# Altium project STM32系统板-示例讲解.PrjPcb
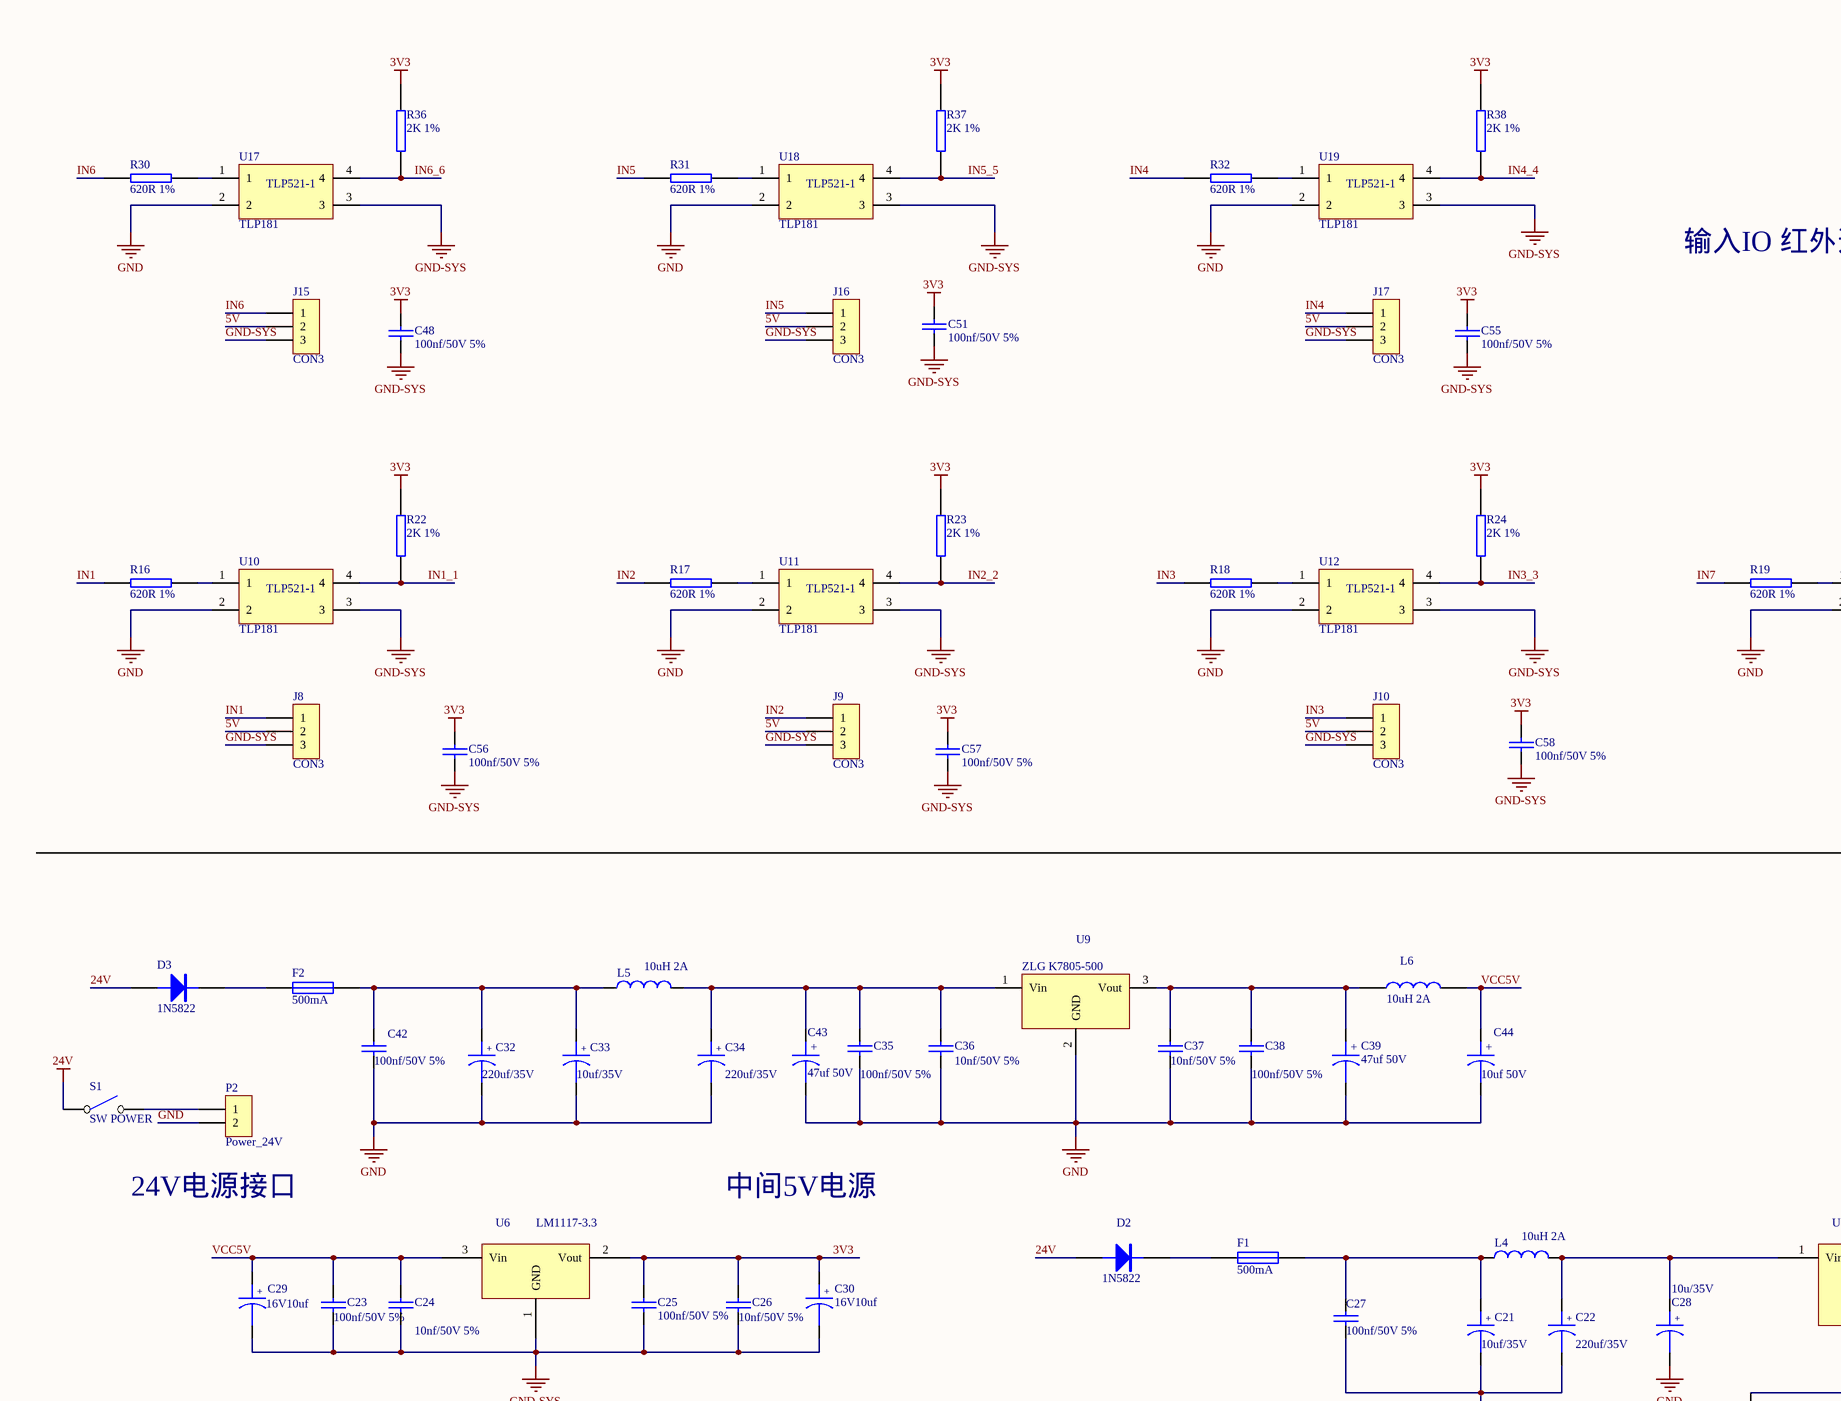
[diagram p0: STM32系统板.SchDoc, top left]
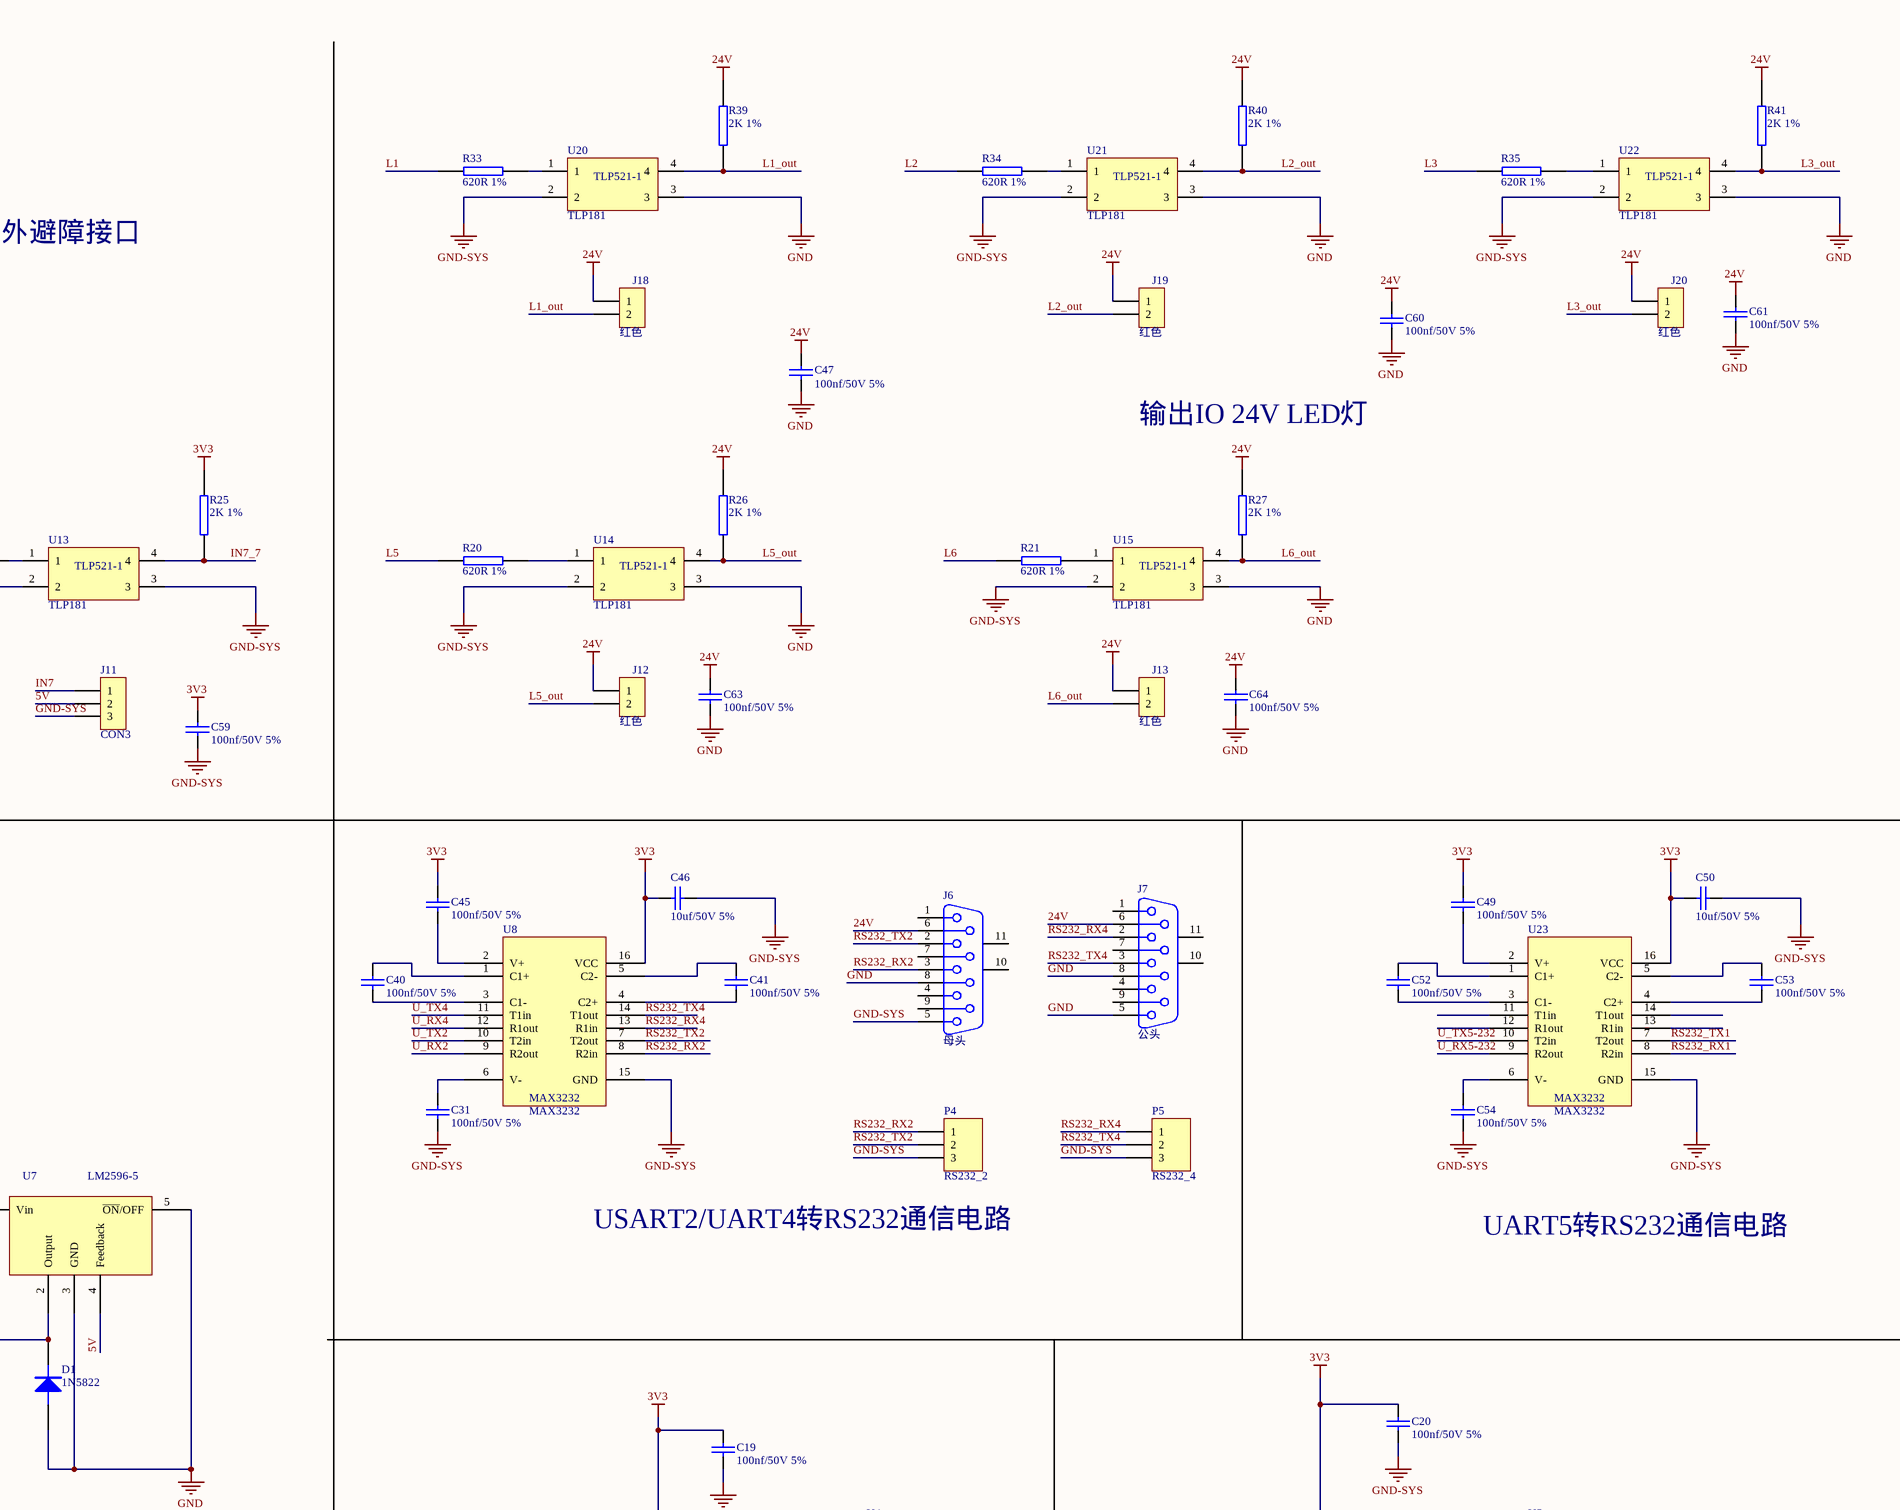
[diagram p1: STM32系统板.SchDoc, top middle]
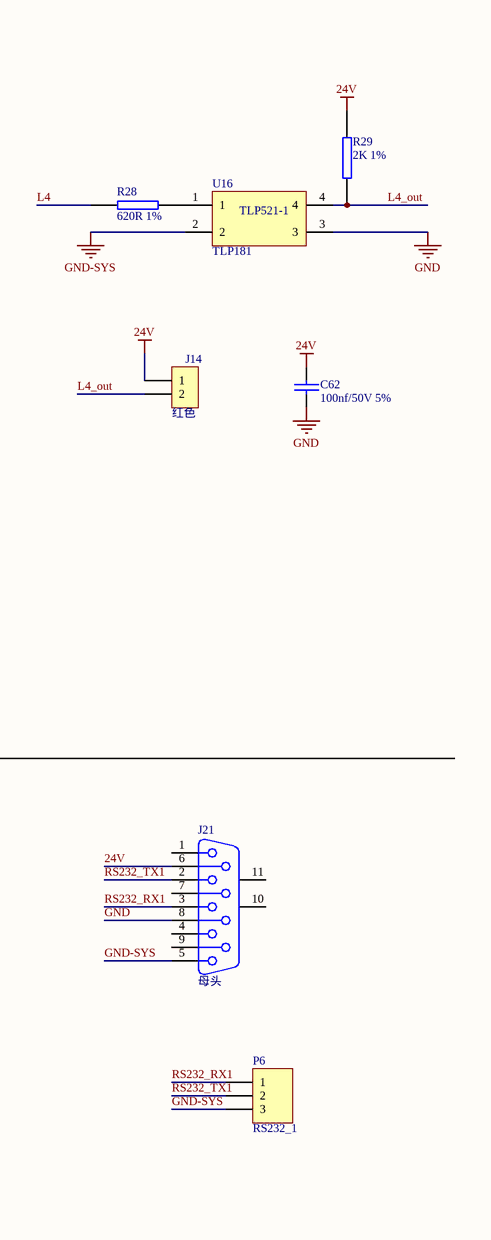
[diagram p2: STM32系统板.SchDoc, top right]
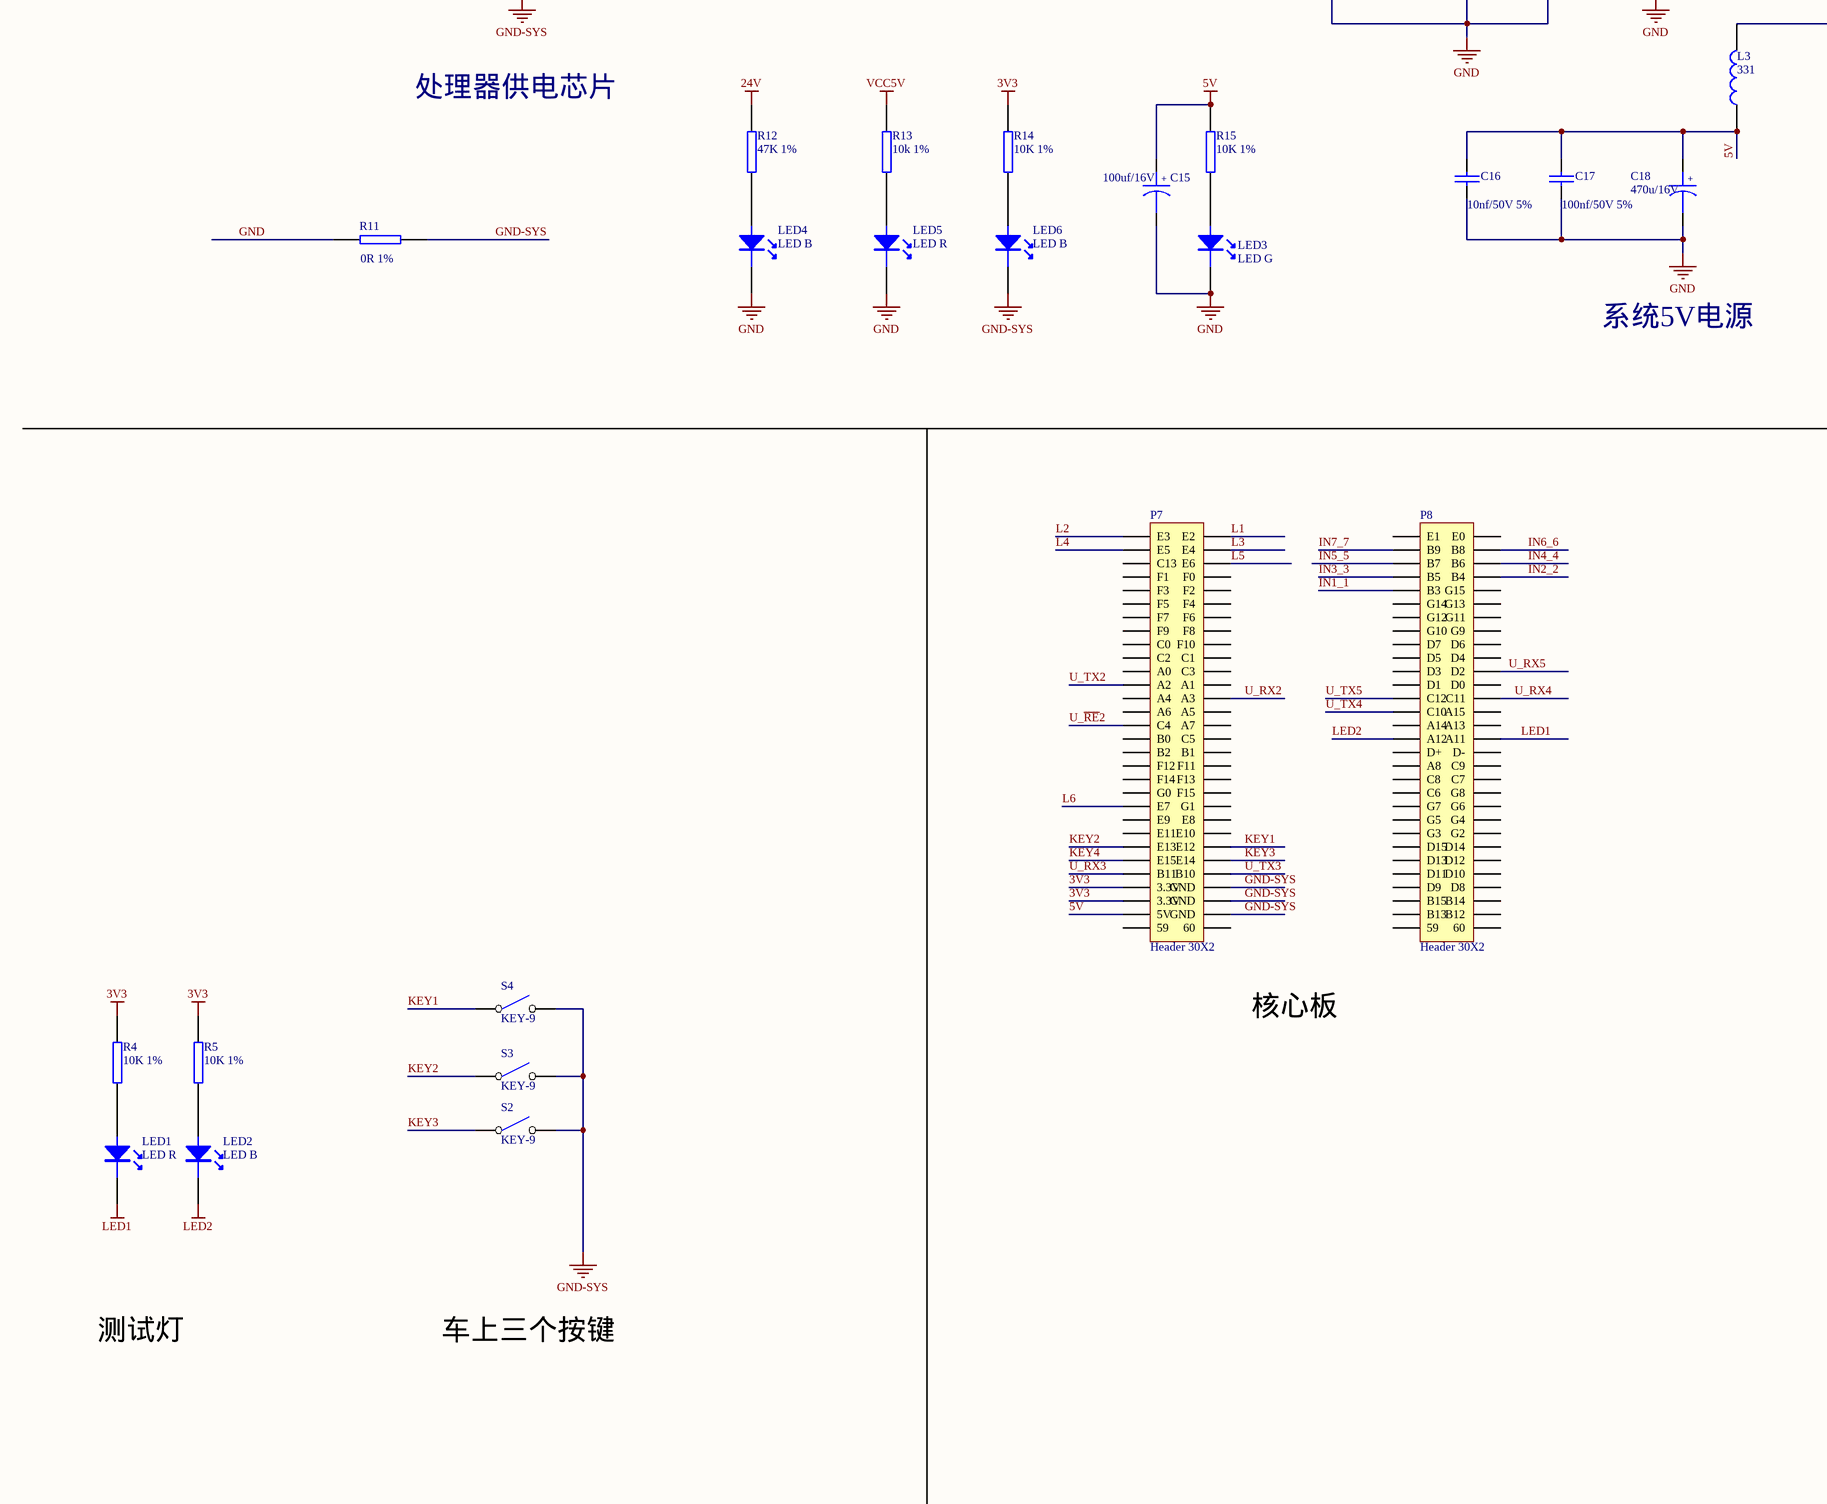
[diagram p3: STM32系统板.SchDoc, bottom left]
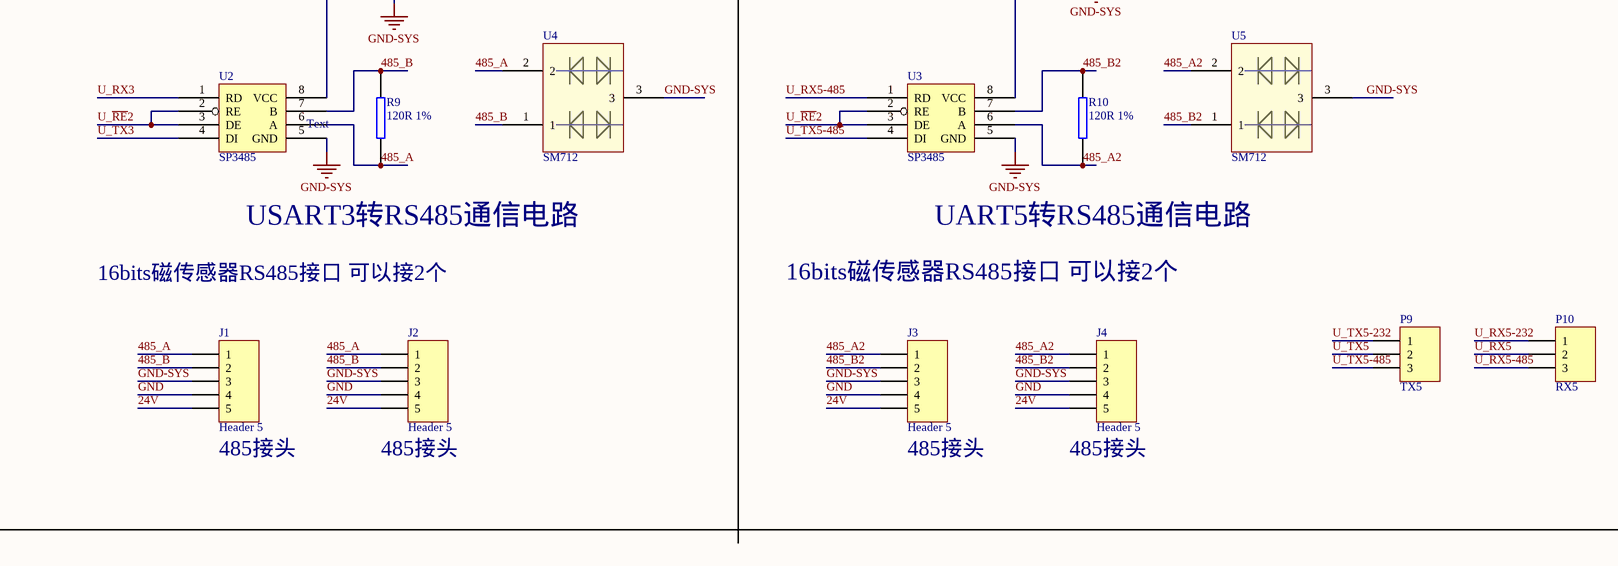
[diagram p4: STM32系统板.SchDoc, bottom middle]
1 sheet, 154 parts. Net scope: global (net labels, ports and power ports of the same name join across sheets).
Board file: STM32系统板.~(30).PcbDoc

## Sheet STM32系统板.SchDoc
size A1; SheetNumber: 0; SheetTotal: 0

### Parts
C15  100uf/16V  [C6.5-35V47uf]
C16  10nf/50V 5%  [0805C]
C17  100nf/50V 5%  [0805C]
C18  470u/16V  [C10-35V330uf]
C19  100nf/50V 5%  [0805C]
C20  100nf/50V 5%  [0805C]
C21  10uf/35V  [C6.5-35V47uf]
C22  220uf/35V  [C6.5-35V47uf]
C23  100nf/50V 5%  [0805C]
C24  10nf/50V 5%  [0805C]
C25  100nf/50V 5%  [0805C]
C26  10nf/50V 5%  [0805C]
C27  100nf/50V 5%  [0805C]
C28  10u/35V  [C6.5-35V47uf]
C29  16V10uf  [1206-2]
C30  16V10uf  [1206-2]
C31  100nf/50V 5%  [0805C]
C32  220uf/35V  [C10-35V330uf]
C33  10uf/35V  [C6.5-35V47uf]
C34  220uf/35V  [C6.5-35V47uf]
C35  100nf/50V 5%  [0805C]
C36  10nf/50V 5%  [0805C]
C37  10nf/50V 5%  [0805C]
C38  100nf/50V 5%  [0805C]
C39  47uf 50V  [C6.5-35V47uf]
C40  100nf/50V 5%  [0805C]
C41  100nf/50V 5%  [0805C]
C42  100nf/50V 5%  [0805C]
C43  47uf 50V  [C6.5-35V47uf]
C44  10uf 50V  [C6.5-35V47uf]
C45  100nf/50V 5%  [0805C]
C46  10uf/50V 5%  [0805C]
C47  100nf/50V 5%  [0805C]
C48  100nf/50V 5%  [0805C]
C49  100nf/50V 5%  [0805C]
C50  10uf/50V 5%  [0805C]
C51  100nf/50V 5%  [0805C]
C52  100nf/50V 5%  [0805C]
C53  100nf/50V 5%  [0805C]
C54  100nf/50V 5%  [0805C]
C55  100nf/50V 5%  [0805C]
C56  100nf/50V 5%  [0805C]
C57  100nf/50V 5%  [0805C]
C58  100nf/50V 5%  [0805C]
C59  100nf/50V 5%  [0805C]
C60  100nf/50V 5%  [0805C]
C61  100nf/50V 5%  [0805C]
C62  100nf/50V 5%  [0805C]
C63  100nf/50V 5%  [0805C]
C64  100nf/50V 5%  [0805C]
D1  1N5822  [SS34]
D2  1N5822  [SS34]
D3  1N5822  [SS34]
F1  500mA  [1812]
F2  500mA  [1812]
J1  Header 5  [CON-5P-3.81]
J2  Header 5  [CON-5P-3.81]
J3  Header 5  [CON-5P-3.81]
J4  Header 5  [CON-5P-3.81]
J6  母头  [DSUB1.385-2H9]
J7  公头  [DSUB1.385-2H9]
J8  CON3  [CON-3P-3.81]
J9  CON3  [CON-3P-3.81]
J10  CON3  [CON-3P-3.81]
J11  CON3  [CON-3P-3.81]
J12  红色  [CON-2P-3.81]
J13  红色  [CON-2P-3.81]
J14  红色  [CON-2P-3.81]
J15  CON3  [CON-3P-3.81]
J16  CON3  [CON-3P-3.81]
J17  CON3  [CON-3P-3.81]
J18  红色  [CON-2P-3.81]
J19  红色  [CON-2P-3.81]
J20  红色  [CON-2P-3.81]
J21  母头  [DSUB1.385-2H9]
L3  331  [LC-10]
L4  value 10uH 2A  [LC-8.2]  (hidden comment: Inductor)
L5  value 10uH 2A  [LC-8.2]  (hidden comment: Inductor)
L6  10uH 2A  [LC-8.2]
LED1  LED R  [0805D]
LED2  LED B  [0805D]
LED3  LED G  [0805D]
LED4  LED B  [0805D]
LED5  LED R  [0805D]
LED6  LED B  [0805D]
P2  Power_24V  [CON-2P-3.81]
P4  RS232_2  [HDR1X3]
P5  RS232_4  [HDR1X3]
P6  RS232_1  [HDR1X3]
P7  Header 30X2  [HDR2X30]
P8  Header 30X2  [HDR2X30]
P9  TX5  [HDR1X3]
P10  RX5  [HDR1X3]
R4  10K 1%  [0805R]
R5  10K 1%  [0805R]
R9  120R 1%  [0805R]
R10  120R 1%  [0805R]
R11  0R 1%  [0805R]
R12  47K 1%  [0805R]
R13  10k 1%  [0805R]
R14  10K 1%  [0805R]
R15  10K 1%  [0805R]
R16  620R 1%  [0805R]
R17  620R 1%  [0805R]
R18  620R 1%  [0805R]
R19  620R 1%  [0805R]
R20  620R 1%  [0805R]
R21  620R 1%  [0805R]
R22  2K 1%  [0805R]
R23  2K 1%  [0805R]
R24  2K 1%  [0805R]
R25  2K 1%  [0805R]
R26  2K 1%  [0805R]
R27  2K 1%  [0805R]
R28  620R 1%  [0805R]
R29  2K 1%  [0805R]
R30  620R 1%  [0805R]
R31  620R 1%  [0805R]
R32  620R 1%  [0805R]
R33  620R 1%  [0805R]
R34  620R 1%  [0805R]
R35  620R 1%  [0805R]
R36  2K 1%  [0805R]
R37  2K 1%  [0805R]
R38  2K 1%  [0805R]
R39  2K 1%  [0805R]
R40  2K 1%  [0805R]
R41  2K 1%  [0805R]
S1  SW POWER  [SIP2]
S2  KEY-9  [SIP2]
S3  KEY-9  [SIP2]
S4  KEY-9  [SIP2]
U2  SP3485  [SO-8]
U3  SP3485  [SO-8]
U4  SM712  [SM712]
U5  SM712  [SM712]
U6  LM1117-3.3  [SOT-223]
U7  LM2596-5  [TO-263-5]
U8  MAX3232  [SO-16]
U9  ZLG K7805-500  [TO-220]
U10  TLP181  [TLP-181]
U11  TLP181  [TLP-181]
U12  TLP181  [TLP-181]
U13  TLP181  [TLP-181]
U14  TLP181  [TLP-181]
U15  TLP181  [TLP-181]
U16  TLP181  [TLP-181]
U17  TLP181  [TLP-181]
U18  TLP181  [TLP-181]
U19  TLP181  [TLP-181]
U20  TLP181  [TLP-181]
U21  TLP181  [TLP-181]
U22  TLP181  [TLP-181]
U23  MAX3232  [SO-16]

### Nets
3V3: C19.2 C20.2 C25.1 C26.1 C30.1 C45.1 C46.1 C48.2 C49.1 C50.1 C51.2 C55.2 C56.2 C57.2 C58.2 C59.2 P7.53(3.3V) P7.55(3.3V) R4.2 R5.2 R14.2 R22.2 R23.2 R24.2 R25.2 R36.2 R37.2 R38.2 U2.8(VCC) U3.8(VCC) U6.2(Vout) U8.16(VCC) U23.16(VCC)
5V: C15.1 C16.1 C17.1 C18.1 J8.2 J9.2 J10.2 J11.2 J15.2 J16.2 J17.2 L3.1 P7.57(5V) R15.2 U7.4(Feedback)
24V: C47.2 C60.2 C61.2 C62.2 C63.2 C64.2 D2.1(A) D3.1(A) J1.5 J2.5 J3.5 J4.5 J6.6 J7.6 J12.1 J13.1 J14.1 J18.1 J19.1 J20.1 J21.6 R12.2 R26.1 R27.1 R29.1 R39.1 R40.1 R41.1 S1.1(COMMON)
GND: C15.2 C16.2 C17.2 C18.2 C21.2 C22.2 C27.2 C28.2 C32.2 C33.2 C34.2 C35.2 C36.2 C37.2 C38.2 C39.2 C42.2 C43.2 C44.2 C47.1 C60.1 C61.1 C62.1 C63.1 C64.1 D1.1(A) J1.4 J2.4 J3.4 J4.4 J6.8 J7.5 J7.8 J21.8 LED3.2 LED4.2 LED5.2 P2.2 R11.1 U7.3(GND) U7.5(~{ON}/OFF) U9.2(GND) U10.2 U11.2 U12.2 U13.2 U14.3 U15.3 U16.3 U17.2 U18.2 U19.2 U20.3 U21.3 U22.3
GND-SYS: C19.1 C20.1 C23.2 C24.2 C25.2 C26.2 C29.2 C30.2 C31.2 C46.2 C48.1 C50.2 C51.1 C54.2 C55.1 C56.1 C57.1 C58.1 C59.1 J1.3 J2.3 J3.3 J4.3 J6.5 J8.3 J9.3 J10.3 J11.3 J15.3 J16.3 J17.3 J21.5 LED6.2 P4.3 P5.3 P6.3 P7.54(GND) P7.56(GND) P7.58(GND) R11.2 S2.2(NO) S3.2(NO) S4.2(NO) U2.5(GND) U3.5(GND) U4.3 U5.3 U6.1(GND) U8.15(GND) U10.3 U11.3 U12.3 U13.3 U14.2 U15.2 U16.2 U17.3 U18.3 U19.3 U20.2 U21.2 U22.2 U23.15(GND)
LED1: LED1.2 P8.32(A11)
LED2: LED2.2 P8.31(A12)
VCC5V: C23.1 C24.1 C29.1 C44.1 L6.2 R13.2 U6.3(Vin)
485_A: J1.1 J2.1 R9.2 U2.6(A) U4.2
485_A2: J3.1 J4.1 R10.2 U3.6(A) U5.2
485_B: J1.2 J2.2 R9.1 U2.7(B) U4.1
485_B2: J3.2 J4.2 R10.1 U3.7(B) U5.1
IN1: J8.1 R16.2
IN1_1: P8.9(B3) R22.1 U10.4
IN2: J9.1 R17.2
IN2_2: P8.8(B4) R23.1 U11.4
IN3: J10.1 R18.2
IN3_3: P8.7(B5) R24.1 U12.4
IN4: J17.1 R32.2
IN4_4: P8.6(B6) R38.1 U19.4
IN5: J16.1 R31.2
IN5_5: P8.5(B7) R37.1 U18.4
IN6: J15.1 R30.2
IN6_6: P8.4(B8) R36.1 U17.4
IN7: J11.1 R19.2
IN7_7: P8.3(B9) R25.1 U13.4
KEY1: P7.48(E12) S4.1(COMMON)
KEY2: P7.47(E13) S3.1(COMMON)
KEY3: P7.50(E14) S2.1(COMMON)
KEY4: P7.49(E15)
L1: P7.2(E2) R33.2
L1_out: J18.2 R39.2 U20.4
L2: P7.1(E3) R34.2
L2_out: J19.2 R40.2 U21.4
L3: P7.4(E4) R35.2
L3_out: J20.2 R41.2 U22.4
L4: P7.3(E5) R28.2
L4_out: J14.2 R29.2 U16.4
L5: P7.6(E6) R20.2
L5_out: J12.2 R26.2 U14.4
L6: P7.41(E7) R21.2
L6_out: J13.2 R27.2 U15.4
RS232_RX1: J21.3 P6.1 U23.8(R2in)
RS232_RX2: J6.3 P4.1 U8.8(R2in)
RS232_RX4: J7.2 P5.1 U8.13(R1in)
RS232_TX1: J21.2 P6.2 U23.7(T2out)
RS232_TX2: J6.2 P4.2 U8.7(T2out)
RS232_TX4: J7.3 P5.2 U8.14(T1out)
U_~{RE}2: P7.29(C4) U2.2(RE) U2.3(DE) U3.2(RE) U3.3(DE)
U_RX2: P7.26(A3) U8.9(R2out)
U_RX3: P7.51(B11) U2.1(RD)
U_RX4: P8.26(C11) U8.12(R1out)
U_RX5: P8.22(D2) P10.2
U_RX5-232: P10.1 U23.9(R2out)
U_RX5-485: P10.3 U3.1(RD)
U_TX2: P7.23(A2) U8.10(T2in)
U_TX3: P7.52(B10) U2.4(DI)
U_TX4: P8.27(C10) U8.11(T1in)
U_TX5: P8.25(C12) P9.2
U_TX5-232: P9.1 U23.10(T2in)
U_TX5-485: P9.3 U3.4(DI)
NetC21_1: C21.1 C27.1 F1.2 L4.1
NetC22_1: C22.1 C28.1 L4.2 U7.1(Vin)
NetC31_1: C31.1 U8.6(V-)
NetC32_1: C32.1 C33.1 C42.1 F2.2 L5.1
NetC34_1: C34.1 C35.1 C36.1 C43.1 L5.2 U9.1(Vin)
NetC37_1: C37.1 C38.1 C39.1 L6.1 U9.3(Vout)
NetC40_1: C40.1 U8.1(C1+)
NetC40_2: C40.2 U8.3(C1-)
NetC41_1: C41.1 U8.5(C2-)
NetC41_2: C41.2 U8.4(C2+)
NetC45_2: C45.2 U8.2(V+)
NetC49_2: C49.2 U23.2(V+)
NetC52_1: C52.1 U23.1(C1+)
NetC52_2: C52.2 U23.3(C1-)
NetC53_1: C53.1 U23.5(C2-)
NetC53_2: C53.2 U23.4(C2+)
NetC54_1: C54.1 U23.6(V-)
NetD1_2: D1.2(K) L3.2 U7.2(Output)
NetD2_2: D2.2(K) F1.1
NetD3_2: D3.2(K) F2.1
NetLED1_1: LED1.1 R4.1
NetLED2_1: LED2.1 R5.1
NetLED3_1: LED3.1 R15.1
NetLED4_1: LED4.1 R12.1
NetLED5_1: LED5.1 R13.1
NetLED6_1: LED6.1 R14.1
NetP2_1: P2.1 S1.2(NO)
NetR16_1: R16.1 U10.1
NetR17_1: R17.1 U11.1
NetR18_1: R18.1 U12.1
NetR19_1: R19.1 U13.1
NetR20_1: R20.1 U14.1
NetR21_1: R21.1 U15.1
NetR28_1: R28.1 U16.1
NetR30_1: R30.1 U17.1
NetR31_1: R31.1 U18.1
NetR32_1: R32.1 U19.1
NetR33_1: R33.1 U20.1
NetR34_1: R34.1 U21.1
NetR35_1: R35.1 U22.1

Not connected (* = marked no-connect by the designer): J6 1 4 7 9 10(MH1) 11(MH2); J7 1 4 7 9 10(MH1) 11(MH2); J21 1 4 7 9 10(MH1) 11(MH2); P7 5(C13) 7(F1) 8(F0) 9(F3) 10(F2) 11(F5) 12(F4) 13(F7) 14(F6) 15(F9) 16(F8) 17(C0) 18(F10) 19(C2) 20(C1) 21(A0) 22(C3) 24(A1) 25(A4) 27(A6) 28(A5) 30(A7) 31(B0) 32(C5) 33(B2) 34(B1) 35(F12) 36(F11) 37(F14) 38(F13) 39(G0) 40(F15) 42(G1) 43(E9) 44(E8) 45(E11) 46(E10) 59 60; P8 1(E1) 2(E0) 10(G15) 11(G14) 12(G13) 13(G12) 14(G11) 15(G10) 16(G9) 17(D7) 18(D6) 19(D5) 20(D4) 21(D3) 23(D1) 24(D0) 28(A15) 29(A14) 30(A13) 33(D+) 34(D-) 35(A8) 36(C9) 37(C8) 38(C7) 39(C6) 40(G8) 41(G7) 42(G6) 43(G5) 44(G4) 45(G3) 46(G2) 47(D15) 48(D14) 49(D13) 50(D12) 51(D11) 52(D10) 53(D9) 54(D8) 55(B15) 56(B14) 57(B13) 58(B12) 59 60; U23 11(T1in) 12(R1out) 13(R1in) 14(T1out)

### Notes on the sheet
- 输入IO 红外避障接口
- 输出IO 24V LED灯
- 24V电源接口
- 中间5V电源
- USART2/UART4转RS232通信电路
- UART5转RS232通信电路
- 处理器供电芯片
- (near U2) Text
- 系统5V电源
- 16bits磁传感器RS485接口 可以接2个
- USART3转RS485通信电路
- UART5转RS485通信电路
- (near J1) 485接头
- (near J2) 485接头
- (near J3) 485接头
- (near J4) 485接头
- 核心板
- 测试灯
- 车上三个按键

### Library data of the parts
C15 C18 C21 C22 C28 C32-C34 C39 C43 C44 = CAPACITOR POL: Capacitor
C16 C17 C19 C20 C23-C27 C31 C35-C38 C40-C42 C45-C64 = CAP: Capacitor
C29 C30 = CAP+
D1-D3 = DIODE
F1 F2 = Fuse 1: Fuse
J1-J4 = Header 5: Header, 5-Pin
J6 J7 J21 = D Connector 9: Receptacle Assembly, 9 Position, Right Angle; PackageDocument: O; Positions: 9
J8-J11 J15-J17 = CON3: Connector
J12-J14 J18-J20 P2 = CON2: Connector
L3 = INDUCTOR
L4 L5 = Inductor: Code_IEC: 1005
L6 = INDUCTOR1
LED1-LED6 = LED
P4-P6 P9 P10 = Header 3: Header, 3-Pin
P7 P8 = Header 30X2: Header, 30-Pin, Dual row
R4 R5 R9-R41 = RES2
S1 = SW SPST
S2-S4 = KEY-2
U2 U3 = MAX485
U6 = LM1117
U7 = LM2596-5.0
U9 = VOLTREG
U10-U22 = TLP521-1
